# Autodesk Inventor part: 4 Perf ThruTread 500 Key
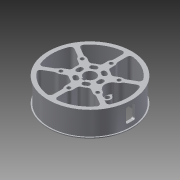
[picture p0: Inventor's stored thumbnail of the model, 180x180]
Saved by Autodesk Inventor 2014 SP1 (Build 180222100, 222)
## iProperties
Created: 2014-07
Part Number: 4 Perf ThruTread 500 Key
Material: Aluminum 6061
Document SubType Name: Modeling
Designer: Michael
Density: 2.71 g/cm^3
Appearance: Aluminum - Flat
Author: Michael
Title: 4 Perf ThruTread 500 Key.STEP
Description: STEP AP203
Creation Date: 2012-12-05
Sending System: SolidWorks 2010
Preprocessor: SwSTEP 2.0
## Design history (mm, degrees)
node "4 Perf ThruTread 500 Key1"
node "Fillet11"
node "Base1"
